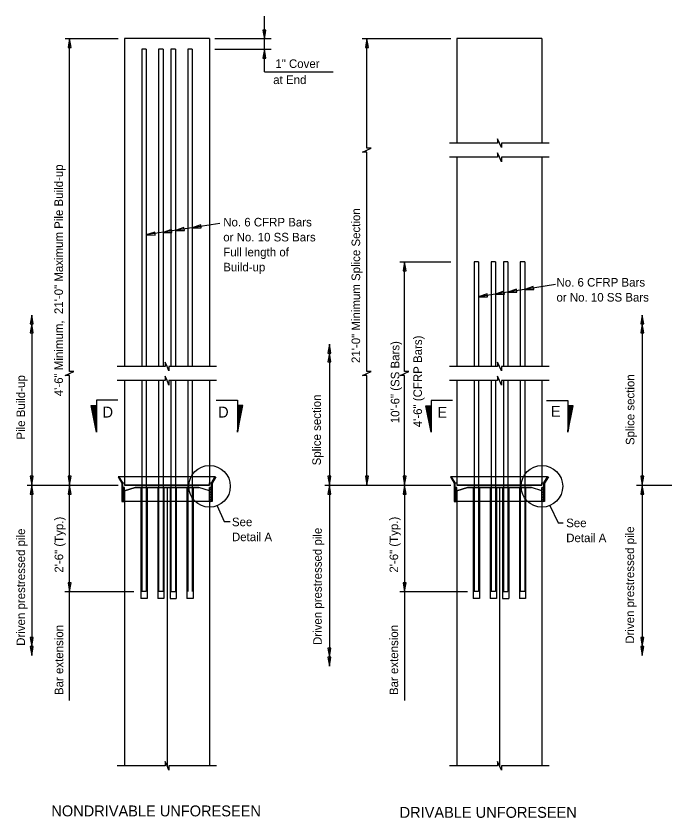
# Model space of a CAD drawing. Extents: x 112304.5 to 112376, y 111876.2 to 111935.5.
# Drawn here: x 112312.55 to 112327.81, y 111905.96 to 111924.81 of the extents above; entities that cross this region are included whole.
import ezdxf

# ---------------------------------------------------------------- set-up
doc = ezdxf.new("R2010")
doc.units = 0
for name, color, linetype in [('Border', 7, 'Continuous'), ('CL_Minor', 7, 'Continuous'), ('Miscellaneous', 7, 'Continuous'), ('Patterning', 7, 'Continuous'), ('PlotBorder_dp', 7, 'Continuous'), ('SheetBorder_dp', 7, 'Continuous'), ('SheetLines_dp', 7, 'Continuous'), ('SteelGirder', 7, 'Continuous'), ('SteelGirder_h', 7, 'Continuous'), ('TextMisc', 7, 'Continuous')]:
    doc.layers.add(name, color=color, linetype=linetype)

msp = doc.modelspace()

# ---------------------------------------------------------------- linework, layer by layer
at = {"layer": 'Border'}
for p, q in [((112313.705, 111924.282), (112314.956, 111924.282)), ((112317.228, 111924.282), (112318.553, 111924.282)), ((112320.69, 111924.282), (112322.77, 111924.282)), ((112317.228, 111924.032), (112318.553, 111924.032)), ((112318.391, 111923.499), (112320.004, 111923.499)), ((112317.342, 111919.937), (112315.611, 111919.664)), ((112321.576, 111919.032), (112322.77, 111919.032)), ((112325.23, 111918.498), (112323.426, 111918.213)), ((112312.921, 111917.782), (112312.921, 111913.782)), ((112327.272, 111917.782), (112327.272, 111913.782)), ((112319.92, 111917.097), (112319.92, 111913.782)), ((112314.441, 111915.03), (112314.331, 111915.655)), ((112314.345, 111915.655), (112314.441, 111915.03)), ((112314.441, 111915.03), (112314.361, 111915.655)), ((112314.38, 111915.655), (112314.441, 111915.03)), ((112314.441, 111915.03), (112314.398, 111915.655)), ((112314.418, 111915.655), (112314.441, 111915.03)), ((112317.784, 111915.655), (112317.76, 111915.03)), ((112317.76, 111915.03), (112317.804, 111915.655)), ((112317.822, 111915.655), (112317.76, 111915.03)), ((112317.76, 111915.03), (112317.84, 111915.655)), ((112317.857, 111915.655), (112317.76, 111915.03)), ((112317.76, 111915.03), (112317.87, 111915.655)), ((112322.31, 111915.026), (112322.2, 111915.651)), ((112322.214, 111915.651), (112322.31, 111915.026)), ((112322.31, 111915.026), (112322.23, 111915.651)), ((112322.249, 111915.651), (112322.31, 111915.026)), ((112322.31, 111915.026), (112322.267, 111915.651)), ((112322.287, 111915.651), (112322.31, 111915.026)), ((112325.545, 111915.651), (112325.521, 111915.026)), ((112325.521, 111915.026), (112325.565, 111915.651)), ((112325.583, 111915.651), (112325.521, 111915.026)), ((112325.521, 111915.026), (112325.601, 111915.651)), ((112325.618, 111915.651), (112325.521, 111915.026)), ((112325.521, 111915.026), (112325.631, 111915.651)), ((112312.811, 111913.782), (112314.956, 111913.782)), ((112312.921, 111913.782), (112312.921, 111909.782)), ((112319.81, 111913.782), (112322.77, 111913.782)), ((112319.92, 111913.782), (112319.92, 111909.532)), ((112321.686, 111913.782), (112321.686, 111911.282)), ((112327.135, 111913.782), (112330.348, 111913.782)), ((112327.272, 111913.782), (112327.272, 111909.782)), ((112317.282, 111913.294), (112317.448, 111912.928)), ((112325.104, 111913.303), (112325.296, 111912.901)), ((112317.448, 111912.928), (112317.588, 111912.928)), ((112325.296, 111912.901), (112325.418, 111912.901)), ((112313.701, 111911.282), (112315.324, 111911.282)), ((112321.576, 111911.282), (112323.164, 111911.282)), ((112321.686, 111911.282), (112321.686, 111908.718))]:
    msp.add_line(p, q, dxfattribs=at)
for points in [[(112318.391, 111923.499), (112318.391, 111924.811)], [(112313.811, 111908.719), (112313.811, 111916.362), (112313.707, 111916.362), (112313.811, 111916.407), (112313.914, 111916.452), (112313.811, 111916.452), (112313.811, 111924.282)], [(112320.8, 111919.032), (112320.8, 111921.612), (112320.696, 111921.612), (112320.8, 111921.657), (112320.903, 111921.702), (112320.8, 111921.702), (112320.8, 111924.282)], [(112325.083, 111921.824), (112323.961, 111921.824), (112323.961, 111921.721), (112323.916, 111921.824), (112323.871, 111921.927), (112323.871, 111921.824), (112322.745, 111921.824)], [(112325.083, 111921.491), (112323.961, 111921.491), (112323.961, 111921.387), (112323.916, 111921.491), (112323.871, 111921.594), (112323.871, 111921.491), (112322.745, 111921.491)], [(112320.8, 111913.782), (112320.8, 111916.362), (112320.696, 111916.362), (112320.8, 111916.407), (112320.903, 111916.452), (112320.8, 111916.452), (112320.8, 111919.032)], [(112321.686, 111913.782), (112321.686, 111916.362), (112321.582, 111916.362), (112321.686, 111916.407), (112321.789, 111916.452), (112321.686, 111916.452), (112321.686, 111919.032)], [(112317.268, 111916.574), (112316.146, 111916.574), (112316.146, 111916.471), (112316.101, 111916.574), (112316.056, 111916.677), (112316.056, 111916.574), (112314.93, 111916.574)], [(112325.083, 111916.574), (112323.961, 111916.574), (112323.961, 111916.471), (112323.916, 111916.574), (112323.871, 111916.677), (112323.871, 111916.574), (112322.745, 111916.574)], [(112317.268, 111916.241), (112316.146, 111916.241), (112316.146, 111916.137), (112316.101, 111916.241), (112316.056, 111916.344), (112316.056, 111916.241), (112314.93, 111916.241)], [(112325.083, 111916.241), (112323.961, 111916.241), (112323.961, 111916.137), (112323.916, 111916.241), (112323.871, 111916.344), (112323.871, 111916.241), (112322.745, 111916.241)], [(112314.941, 111915.78), (112314.441, 111915.78), (112314.441, 111915.03), (112314.316, 111915.655), (112314.441, 111915.655)], [(112317.26, 111915.78), (112317.76, 111915.78), (112317.76, 111915.03), (112317.885, 111915.655), (112317.76, 111915.655)], [(112322.81, 111915.776), (112322.31, 111915.776), (112322.31, 111915.026), (112322.185, 111915.651), (112322.31, 111915.651)], [(112325.021, 111915.776), (112325.521, 111915.776), (112325.521, 111915.026), (112325.646, 111915.651), (112325.521, 111915.651)], [(112317.268, 111907.185), (112316.146, 111907.185), (112316.146, 111907.081), (112316.101, 111907.185), (112316.056, 111907.288), (112316.056, 111907.185), (112314.93, 111907.185)], [(112325.083, 111907.185), (112323.961, 111907.185), (112323.961, 111907.081), (112323.916, 111907.185), (112323.871, 111907.288), (112323.871, 111907.185), (112322.745, 111907.185)]]:
    msp.add_lwpolyline(points, dxfattribs=at)
for points in [[(112318.391, 111924.27), (112318.426, 111924.479), (112318.356, 111924.479)], [(112313.811, 111924.282), (112313.775, 111924.074), (112313.846, 111924.074)], [(112320.8, 111924.282), (112320.764, 111924.074), (112320.835, 111924.074)], [(112318.391, 111924.032), (112318.356, 111923.824), (112318.426, 111923.824)], [(112316.299, 111919.772), (112316.51, 111919.77), (112316.499, 111919.839)], [(112316.695, 111919.834), (112316.906, 111919.832), (112316.895, 111919.902)], [(112315.611, 111919.664), (112315.822, 111919.661), (112315.811, 111919.731)], [(112316.007, 111919.726), (112316.218, 111919.724), (112316.207, 111919.793)], [(112321.686, 111919.032), (112321.65, 111918.824), (112321.721, 111918.824)], [(112323.822, 111918.276), (112324.033, 111918.273), (112324.022, 111918.343)], [(112324.114, 111918.322), (112324.325, 111918.319), (112324.314, 111918.389)], [(112324.51, 111918.384), (112324.721, 111918.382), (112324.71, 111918.451)], [(112323.426, 111918.213), (112323.637, 111918.211), (112323.626, 111918.28)], [(112312.921, 111917.782), (112312.886, 111917.574), (112312.956, 111917.574)], [(112327.272, 111917.782), (112327.237, 111917.574), (112327.307, 111917.574)], [(112312.921, 111917.574), (112312.886, 111917.366), (112312.956, 111917.366)], [(112327.272, 111917.574), (112327.237, 111917.366), (112327.307, 111917.366)], [(112319.92, 111917.097), (112319.884, 111916.889), (112319.955, 111916.889)], [(112319.92, 111916.889), (112319.884, 111916.681), (112319.955, 111916.681)], [(112312.921, 111913.782), (112312.956, 111913.991), (112312.886, 111913.991)], [(112313.811, 111913.782), (112313.846, 111913.991), (112313.775, 111913.991)], [(112319.92, 111913.782), (112319.955, 111913.991), (112319.884, 111913.991)], [(112320.8, 111913.782), (112320.835, 111913.991), (112320.764, 111913.991)], [(112321.686, 111913.782), (112321.721, 111913.991), (112321.65, 111913.991)], [(112327.272, 111913.782), (112327.307, 111913.991), (112327.237, 111913.991)], [(112312.921, 111913.782), (112312.886, 111913.574), (112312.956, 111913.574)], [(112313.811, 111913.782), (112313.775, 111913.574), (112313.846, 111913.574)], [(112319.92, 111913.782), (112319.884, 111913.574), (112319.955, 111913.574)], [(112321.686, 111913.782), (112321.65, 111913.574), (112321.721, 111913.574)], [(112327.272, 111913.782), (112327.237, 111913.574), (112327.307, 111913.574)], [(112313.811, 111911.282), (112313.846, 111911.491), (112313.775, 111911.491)], [(112321.686, 111911.282), (112321.721, 111911.491), (112321.65, 111911.491)], [(112312.921, 111909.991), (112312.956, 111910.199), (112312.886, 111910.199)], [(112327.272, 111909.991), (112327.307, 111910.199), (112327.237, 111910.199)], [(112312.921, 111909.782), (112312.956, 111909.991), (112312.886, 111909.991)], [(112319.92, 111909.74), (112319.955, 111909.948), (112319.884, 111909.948)], [(112327.272, 111909.782), (112327.307, 111909.991), (112327.237, 111909.991)], [(112319.92, 111909.532), (112319.955, 111909.74), (112319.884, 111909.74)]]:
    msp.add_lwpolyline(points, close=True, dxfattribs=at)
for centre in [(112317.1, 111913.756), (112324.914, 111913.756)]:
    msp.add_circle(centre, 0.489, dxfattribs=at)
at = {"layer": 'CL_Minor'}
for p, q in [((112316.101, 111913.72), (112316.101, 111907.185)), ((112323.916, 111913.72), (112323.916, 111907.185))]:
    msp.add_line(p, q, dxfattribs=at)
at = {"layer": 'Miscellaneous'}
for p, q in [((112315.059, 111913.719), (112315.07, 111913.73)), ((112315.059, 111913.66), (112315.101, 111913.702)), ((112315.059, 111913.601), (112315.101, 111913.643)), ((112317.101, 111913.719), (112317.112, 111913.73)), ((112317.101, 111913.66), (112317.143, 111913.702)), ((112317.101, 111913.601), (112317.143, 111913.643)), ((112322.874, 111913.719), (112322.885, 111913.73)), ((112322.874, 111913.66), (112322.916, 111913.702)), ((112322.874, 111913.601), (112322.916, 111913.643)), ((112324.916, 111913.719), (112324.927, 111913.73)), ((112324.916, 111913.66), (112324.957, 111913.702)), ((112324.916, 111913.601), (112324.957, 111913.643)), ((112315.059, 111913.542), (112315.101, 111913.584)), ((112315.059, 111913.483), (112315.101, 111913.525)), ((112315.059, 111913.424), (112315.101, 111913.466)), ((112315.091, 111913.397), (112315.101, 111913.407)), ((112317.101, 111913.542), (112317.143, 111913.584)), ((112317.101, 111913.483), (112317.143, 111913.525)), ((112317.101, 111913.424), (112317.143, 111913.466)), ((112317.132, 111913.397), (112317.143, 111913.407)), ((112322.874, 111913.542), (112322.916, 111913.584)), ((112322.874, 111913.483), (112322.916, 111913.525)), ((112322.874, 111913.424), (112322.916, 111913.466)), ((112322.905, 111913.397), (112322.916, 111913.407)), ((112324.916, 111913.542), (112324.957, 111913.584)), ((112324.916, 111913.483), (112324.957, 111913.525)), ((112324.916, 111913.424), (112324.957, 111913.466)), ((112324.947, 111913.397), (112324.957, 111913.407))]:
    msp.add_line(p, q, dxfattribs=at)
for points in [[(112315.059, 111913.834), (112315.101, 111913.834), (112315.101, 111913.782), (112317.101, 111913.782), (112317.101, 111913.834), (112317.143, 111913.834), (112317.143, 111913.73), (112317.101, 111913.73), (112317.101, 111913.647), (112316.851, 111913.73), (112315.351, 111913.73), (112315.101, 111913.647), (112315.101, 111913.73), (112315.059, 111913.73)], [(112322.874, 111913.834), (112322.916, 111913.834), (112322.916, 111913.782), (112324.916, 111913.782), (112324.916, 111913.834), (112324.957, 111913.834), (112324.957, 111913.73), (112324.916, 111913.73), (112324.916, 111913.647), (112324.666, 111913.73), (112323.166, 111913.73), (112322.916, 111913.647), (112322.916, 111913.73), (112322.874, 111913.73)], [(112315.101, 111913.73), (112315.059, 111913.73), (112315.059, 111913.397), (112315.101, 111913.397)], [(112317.101, 111913.73), (112317.143, 111913.73), (112317.143, 111913.397), (112317.101, 111913.397)], [(112322.916, 111913.73), (112322.874, 111913.73), (112322.874, 111913.397), (112322.916, 111913.397)], [(112324.916, 111913.73), (112324.957, 111913.73), (112324.957, 111913.397), (112324.916, 111913.397)]]:
    msp.add_lwpolyline(points, close=True, dxfattribs=at)
at = {"layer": 'Patterning'}
for p, q in [((112323.426, 111911.282), (112323.322, 111911.282)), ((112323.822, 111911.282), (112323.718, 111911.282)), ((112324.009, 111911.282), (112324.114, 111911.282)), ((112324.51, 111911.282), (112324.405, 111911.282))]:
    msp.add_line(p, q, dxfattribs=at)
at = {"layer": 'PlotBorder_dp'}
for p, q in [((112317.101, 111924.282), (112315.101, 111924.282)), ((112315.101, 111924.282), (112315.101, 111916.574)), ((112317.101, 111924.282), (112317.101, 111916.574)), ((112324.916, 111924.282), (112322.916, 111924.282)), ((112322.916, 111924.282), (112322.916, 111921.824)), ((112324.916, 111924.282), (112324.916, 111921.824)), ((112322.916, 111921.491), (112322.916, 111916.574)), ((112324.916, 111921.491), (112324.916, 111916.574)), ((112315.101, 111916.241), (112315.101, 111913.782)), ((112317.101, 111916.241), (112317.101, 111913.782)), ((112322.916, 111916.241), (112322.916, 111913.782)), ((112324.916, 111916.241), (112324.916, 111913.782)), ((112317.101, 111913.782), (112315.101, 111913.782)), ((112324.916, 111913.782), (112322.916, 111913.782)), ((112315.101, 111913.647), (112315.351, 111913.73)), ((112315.101, 111913.647), (112315.101, 111907.185)), ((112315.351, 111913.73), (112316.851, 111913.73)), ((112317.101, 111913.647), (112316.851, 111913.73)), ((112317.101, 111913.647), (112317.101, 111907.185)), ((112322.916, 111913.647), (112323.166, 111913.73)), ((112322.916, 111913.647), (112322.916, 111907.185)), ((112323.166, 111913.73), (112324.666, 111913.73)), ((112324.916, 111913.647), (112324.666, 111913.73)), ((112324.916, 111913.647), (112324.916, 111907.185))]:
    msp.add_line(p, q, dxfattribs=at)
at = {"layer": 'SheetLines_dp'}
for p, q in [((112315.611, 111924.032), (112315.507, 111924.032)), ((112315.507, 111924.032), (112315.507, 111916.574)), ((112315.611, 111924.032), (112315.611, 111916.574)), ((112316.007, 111924.032), (112315.903, 111924.032)), ((112315.903, 111924.032), (112315.903, 111916.574)), ((112316.007, 111924.032), (112316.007, 111916.574)), ((112316.299, 111924.032), (112316.194, 111924.032)), ((112316.194, 111924.032), (112316.194, 111916.574)), ((112316.299, 111924.032), (112316.299, 111916.574)), ((112316.695, 111924.032), (112316.59, 111924.032)), ((112316.59, 111924.032), (112316.59, 111916.574)), ((112316.695, 111924.032), (112316.695, 111916.574)), ((112323.426, 111919.032), (112323.322, 111919.032)), ((112323.322, 111919.032), (112323.322, 111916.574)), ((112323.426, 111919.032), (112323.426, 111916.574)), ((112323.822, 111919.032), (112323.718, 111919.032)), ((112323.718, 111919.032), (112323.718, 111916.574)), ((112323.822, 111919.032), (112323.822, 111916.574)), ((112324.114, 111919.032), (112324.009, 111919.032)), ((112324.009, 111919.032), (112324.009, 111916.574)), ((112324.114, 111919.032), (112324.114, 111916.574)), ((112324.51, 111919.032), (112324.405, 111919.032)), ((112324.405, 111919.032), (112324.405, 111916.574)), ((112324.51, 111919.032), (112324.51, 111916.574)), ((112315.507, 111916.241), (112315.507, 111911.282)), ((112315.611, 111916.241), (112315.611, 111911.282)), ((112315.903, 111916.241), (112315.903, 111911.282)), ((112316.007, 111916.241), (112316.007, 111911.282)), ((112316.194, 111916.241), (112316.194, 111911.282)), ((112316.299, 111916.241), (112316.299, 111911.282)), ((112316.59, 111916.241), (112316.59, 111911.282)), ((112316.695, 111916.241), (112316.695, 111911.282)), ((112323.322, 111916.241), (112323.322, 111911.282)), ((112323.426, 111916.241), (112323.426, 111911.282)), ((112323.718, 111916.241), (112323.718, 111911.282)), ((112323.822, 111916.241), (112323.822, 111911.282)), ((112324.009, 111916.241), (112324.009, 111911.282)), ((112324.114, 111916.241), (112324.114, 111911.282)), ((112324.405, 111916.241), (112324.405, 111911.282)), ((112324.51, 111916.241), (112324.51, 111911.282)), ((112315.611, 111911.282), (112315.507, 111911.282)), ((112316.007, 111911.282), (112315.903, 111911.282)), ((112316.194, 111911.282), (112316.299, 111911.282))]:
    msp.add_line(p, q, dxfattribs=at)
at = {"layer": 'SteelGirder'}
for p, q in [((112315.101, 111913.98), (112314.975, 111913.98)), ((112317.227, 111913.98), (112317.101, 111913.98)), ((112322.916, 111913.98), (112322.79, 111913.98)), ((112325.042, 111913.98), (112324.916, 111913.98)), ((112315.101, 111913.397), (112315.059, 111913.397)), ((112317.143, 111913.397), (112317.101, 111913.397)), ((112322.916, 111913.397), (112322.874, 111913.397)), ((112324.957, 111913.397), (112324.916, 111913.397))]:
    msp.add_line(p, q, dxfattribs=at)
for points in [[(112314.975, 111913.98), (112314.951, 111913.98), (112315.038, 111913.829), (112315.038, 111913.397), (112315.059, 111913.397), (112315.059, 111913.834)], [(112317.227, 111913.98), (112317.251, 111913.98), (112317.163, 111913.829), (112317.163, 111913.397), (112317.143, 111913.397), (112317.143, 111913.834)], [(112322.79, 111913.98), (112322.766, 111913.98), (112322.853, 111913.829), (112322.853, 111913.397), (112322.874, 111913.397), (112322.874, 111913.834)], [(112325.042, 111913.98), (112325.066, 111913.98), (112324.978, 111913.829), (112324.978, 111913.397), (112324.957, 111913.397), (112324.957, 111913.834)]]:
    msp.add_lwpolyline(points, close=True, dxfattribs=at)
at = {"layer": 'SteelGirder_h'}
for p, q in [((112317.101, 111913.98), (112315.101, 111913.98)), ((112324.916, 111913.98), (112322.916, 111913.98)), ((112317.101, 111913.397), (112315.101, 111913.397)), ((112324.916, 111913.397), (112322.916, 111913.397))]:
    msp.add_line(p, q, dxfattribs=at)
at = {"layer": 'TextMisc'}
for p, q in [((112315.486, 111913.73), (112315.486, 111911.116)), ((112315.632, 111913.73), (112315.632, 111911.116)), ((112315.882, 111913.73), (112315.882, 111911.116)), ((112316.028, 111913.73), (112316.028, 111911.116)), ((112316.174, 111913.73), (112316.174, 111911.116)), ((112316.319, 111913.73), (112316.319, 111911.116)), ((112316.57, 111913.73), (112316.57, 111911.116)), ((112316.715, 111913.73), (112316.715, 111911.116)), ((112323.301, 111913.73), (112323.301, 111911.116)), ((112323.447, 111913.73), (112323.447, 111911.116)), ((112323.697, 111913.73), (112323.697, 111911.116)), ((112323.843, 111913.73), (112323.843, 111911.116)), ((112323.989, 111913.73), (112323.989, 111911.116)), ((112324.134, 111913.73), (112324.134, 111911.116)), ((112324.385, 111913.73), (112324.385, 111911.116)), ((112324.53, 111913.73), (112324.53, 111911.116)), ((112315.632, 111911.116), (112315.486, 111911.116)), ((112316.028, 111911.116), (112315.882, 111911.116)), ((112316.174, 111911.116), (112316.319, 111911.116)), ((112316.715, 111911.116), (112316.57, 111911.116)), ((112323.447, 111911.116), (112323.301, 111911.116)), ((112323.843, 111911.116), (112323.697, 111911.116)), ((112323.989, 111911.116), (112324.134, 111911.116)), ((112324.53, 111911.116), (112324.385, 111911.116))]:
    msp.add_line(p, q, dxfattribs=at)

# ---------------------------------------------------------------- texts
at = {"layer": 'Border'}
for s, height, p in [('No. 6 CFRP Bars', 0.2016, (112317.423, 111919.865)), ('or No. 10 SS Bars', 0.2016, (112317.423, 111919.513)), ('Full length of', 0.2016, (112317.423, 111919.161)), ('Build-up', 0.2016, (112317.423, 111918.809)), ('No. 6 CFRP Bars', 0.2016, (112325.257, 111918.451)), ('or No. 10 SS Bars', 0.2016, (112325.257, 111918.099)), ('See', 0.2016, (112317.627, 111912.818)), ('See', 0.2016, (112325.485, 111912.795)), ('Detail A', 0.2016, (112317.627, 111912.466)), ('Detail A', 0.2016, (112325.485, 111912.443)), ('NONDRIVABLE UNFORESEEN', 0.256, (112313.382, 111905.997)), ('DRIVABLE UNFORESEEN', 0.256, (112321.569, 111905.963))]:
    msp.add_text(s, height=height, dxfattribs=at).set_placement(p)
at = {"layer": 'SheetBorder_dp'}
for s, height, p in [('1" Cover', 0.2016, (112318.647, 111923.591)), ('at End', 0.2016, (112318.598, 111923.212)), ('D', 0.256, (112314.585, 111915.373)), ('D', 0.256, (112317.302, 111915.373)), ('E', 0.256, (112322.457, 111915.368)), ('E', 0.256, (112325.126, 111915.392))]:
    msp.add_text(s, height=height, dxfattribs=at).set_placement(p)
for s, p in [('4\'-6" Minimum,  21\'-0" Maximum Pile Build-up', (112313.655, 111915.875)), ('21\'-0" Minimum Splice Section', (112320.641, 111916.654)), ('4\'-6" (CFRP Bars)', (112322.094, 111915.145)), ('10\'-6" (SS Bars)', (112321.564, 111915.24)), ('Pile Build-up', (112312.764, 111914.855)), ('Splice section', (112327.089, 111914.726)), ('Splice section', (112319.719, 111914.25)), ('2\'-6" (Typ.)', (112313.66, 111911.726)), ('2\'-6" (Typ.)', (112321.535, 111911.726)), ('Driven prestressed pile', (112312.764, 111910.006)), ('Driven prestressed pile', (112319.739, 111910.026)), ('Driven prestressed pile', (112327.082, 111910.056)), ('Bar extension', (112313.661, 111908.849)), ('Bar extension', (112321.535, 111908.849))]:
    msp.add_text(s, height=0.2016, rotation=90, dxfattribs=at).set_placement(p)

doc.saveas('drawing.dxf')
